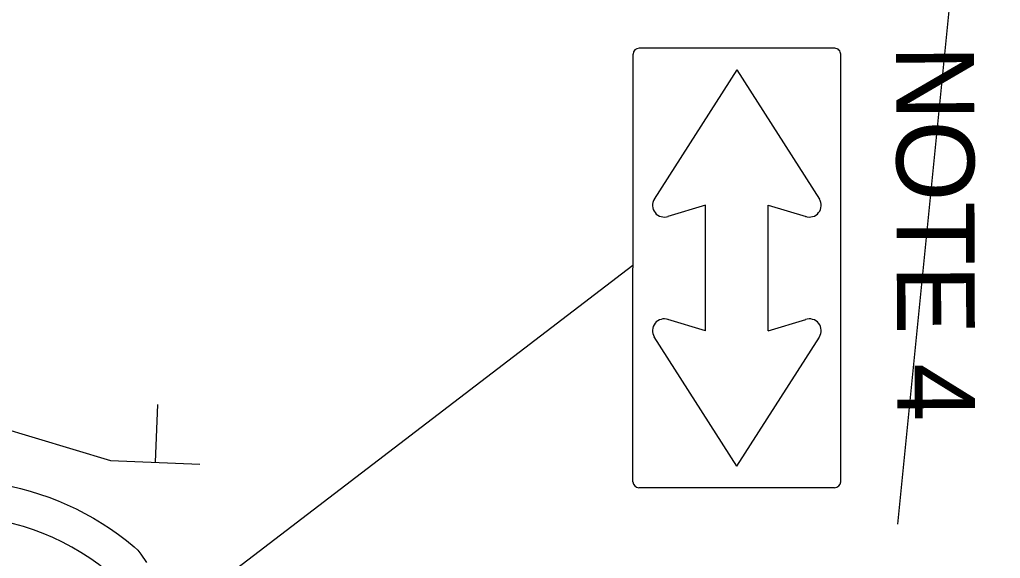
# Model space of a CAD drawing. Extents: x 2096670 to 2098561, y 684033 to 689893.
# Drawn here: x 2097702.4 to 2097853.5, y 686892.9 to 686976 of the extents above; entities that cross this region are included whole.
import ezdxf

# ---------------------------------------------------------------- set-up
doc = ezdxf.new("R2010")
doc.units = 0
for name, color, linetype in [('Exist Sign E Two Direction', 7, 'Continuous'), ('Old_Level_63', 7, 'Continuous'), ('Prop DSN Text', 7, 'Continuous'), ('Prop Sign E One Way_Right CELL', 7, 'Continuous'), ('Scratch_Level_3', 7, 'Continuous')]:
    doc.layers.add(name, color=color, linetype=linetype)

msp = doc.modelspace()

# ---------------------------------------------------------------- linework, layer by layer
at = {"layer": 'Exist Sign E Two Direction'}
for p, q in [((2097828, 686971.59), (2097797.85, 686971.6)), ((2097796.9, 686904.77), (2097796.92, 686970.67)), ((2097828.92, 686904.77), (2097828.93, 686970.66)), ((2097812.93, 686968.25), (2097800.2, 686948.35)), ((2097812.93, 686968.25), (2097825.64, 686948.35)), ((2097808.08, 686947.41), (2097802.26, 686945.65)), ((2097808.08, 686928.03), (2097808.08, 686947.41)), ((2097817.76, 686947.41), (2097823.58, 686945.65)), ((2097817.76, 686928.02), (2097817.76, 686947.41)), ((2097796.91, 686938.1), (2097724.46, 686882.69)), ((2097808.08, 686928.03), (2097802.26, 686929.79)), ((2097817.76, 686928.02), (2097823.57, 686929.79)), ((2097812.91, 686907.19), (2097800.2, 686927.09)), ((2097812.91, 686907.19), (2097825.64, 686927.08)), ((2097827.99, 686903.84), (2097797.84, 686903.84))]:
    msp.add_line(p, q, dxfattribs=at)
for centre, radius, start, end in [((2097797.85, 686970.67), 0.931, 89.9899, 179.9899), ((2097828, 686970.66), 0.931, 359.9899, 89.9899), ((2097801.73, 686947.38), 1.81, 147.4015, 289.8217), ((2097824.11, 686947.38), 1.81, 250.158, 32.5782), ((2097801.73, 686928.06), 1.81, 70.158, 212.5782), ((2097824.11, 686928.06), 1.81, 327.4015, 109.8217), ((2097797.84, 686904.77), 0.931, 179.9899, 269.9899), ((2097827.99, 686904.77), 0.931, 269.9899, 359.9899)]:
    msp.add_arc(centre, radius, start, end, dxfattribs=at)
at = {"layer": 'Old_Level_63'}
msp.add_lwpolyline([(2097701.03, 686904.06), (2097702.52, 686903.72), (2097704, 686903.32), (2097705.46, 686902.87), (2097706.9, 686902.37), (2097708.33, 686901.82), (2097709.73, 686901.22), (2097711.11, 686900.57), (2097712.47, 686899.87), (2097713.8, 686899.13), (2097715.11, 686898.34), (2097716.39, 686897.5), (2097717.64, 686896.62), (2097718.85, 686895.69), (2097720.03, 686894.73), (2097720.59, 686894.2), (2097721.08, 686893.61), (2097721.97, 686892.34)], dxfattribs=at)
msp.add_arc((2097691.92, 686861.49), 38.01, 48.3146, 126.7544, dxfattribs=at)
at = {"layer": 'Prop DSN Text'}
for p, q in [((2097723.34, 686907.76), (2097723.69, 686916.67)), ((2097716.41, 686908.02), (2097730.17, 686907.5))]:
    msp.add_line(p, q, dxfattribs=at)
at = {"layer": 'Prop Sign E One Way_Right CELL'}
msp.add_line((2097544.37, 686959.78), (2097716.41, 686908.02), dxfattribs=at)
at = {"layer": 'Scratch_Level_3'}
msp.add_line((2097853.53, 687057.21), (2097837.69, 686898.25), dxfattribs=at)

# ---------------------------------------------------------------- texts
at = {"layer": 'Prop DSN Text'}
msp.add_text('SEE NOTE 4', height=12, rotation=270.1752, dxfattribs=at).set_placement((2097837.35, 687008.6))

doc.saveas('drawing.dxf')
